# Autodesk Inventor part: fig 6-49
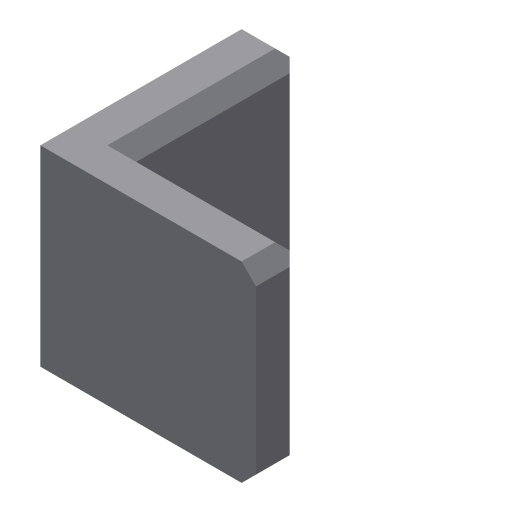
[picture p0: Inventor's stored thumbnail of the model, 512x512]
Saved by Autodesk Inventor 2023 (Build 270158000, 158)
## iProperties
Created: 2009-09
Part Number: fig 6-49
Document SubType Name: Modeling
Designer: Sham
Density: 1 g/cm^3
Material: Generic
Appearance: Default
Author: Sham
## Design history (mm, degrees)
sketch "Sketch1"
  geometry: L1 (1.789, 30)-(1.789, -5); L2 (1.789, -5)-(36.789, -5); L3 (36.789, -5)-(36.789, -15); L4 (36.789, -15)-(-8.211, -15); L5 (-8.211, -15)-(-8.211, 30); L6 (-8.211, 30)-(1.789, 30)
  constraints: 12 end point, 6 perpendicular
  dimensions: "d0" = 10 distance of L5.end L1.start; "d1" = 35 distance of L1.start L1.end; "d2" = 45 distance of L3.end L4.end; "d3" = 10 distance of L2.end L3.end (derived)
extrude "Extrusion1" new body sketch "Sketch1" distance "d4" = 40; taper "d5" = 0 deg
chamfer "Chamfer1" distance "d6" = 3; stored, may be unused: second distance "d7" = 2, angle "d8" = 45 deg
body "Solid1"
other parameters: "d1" = 35
